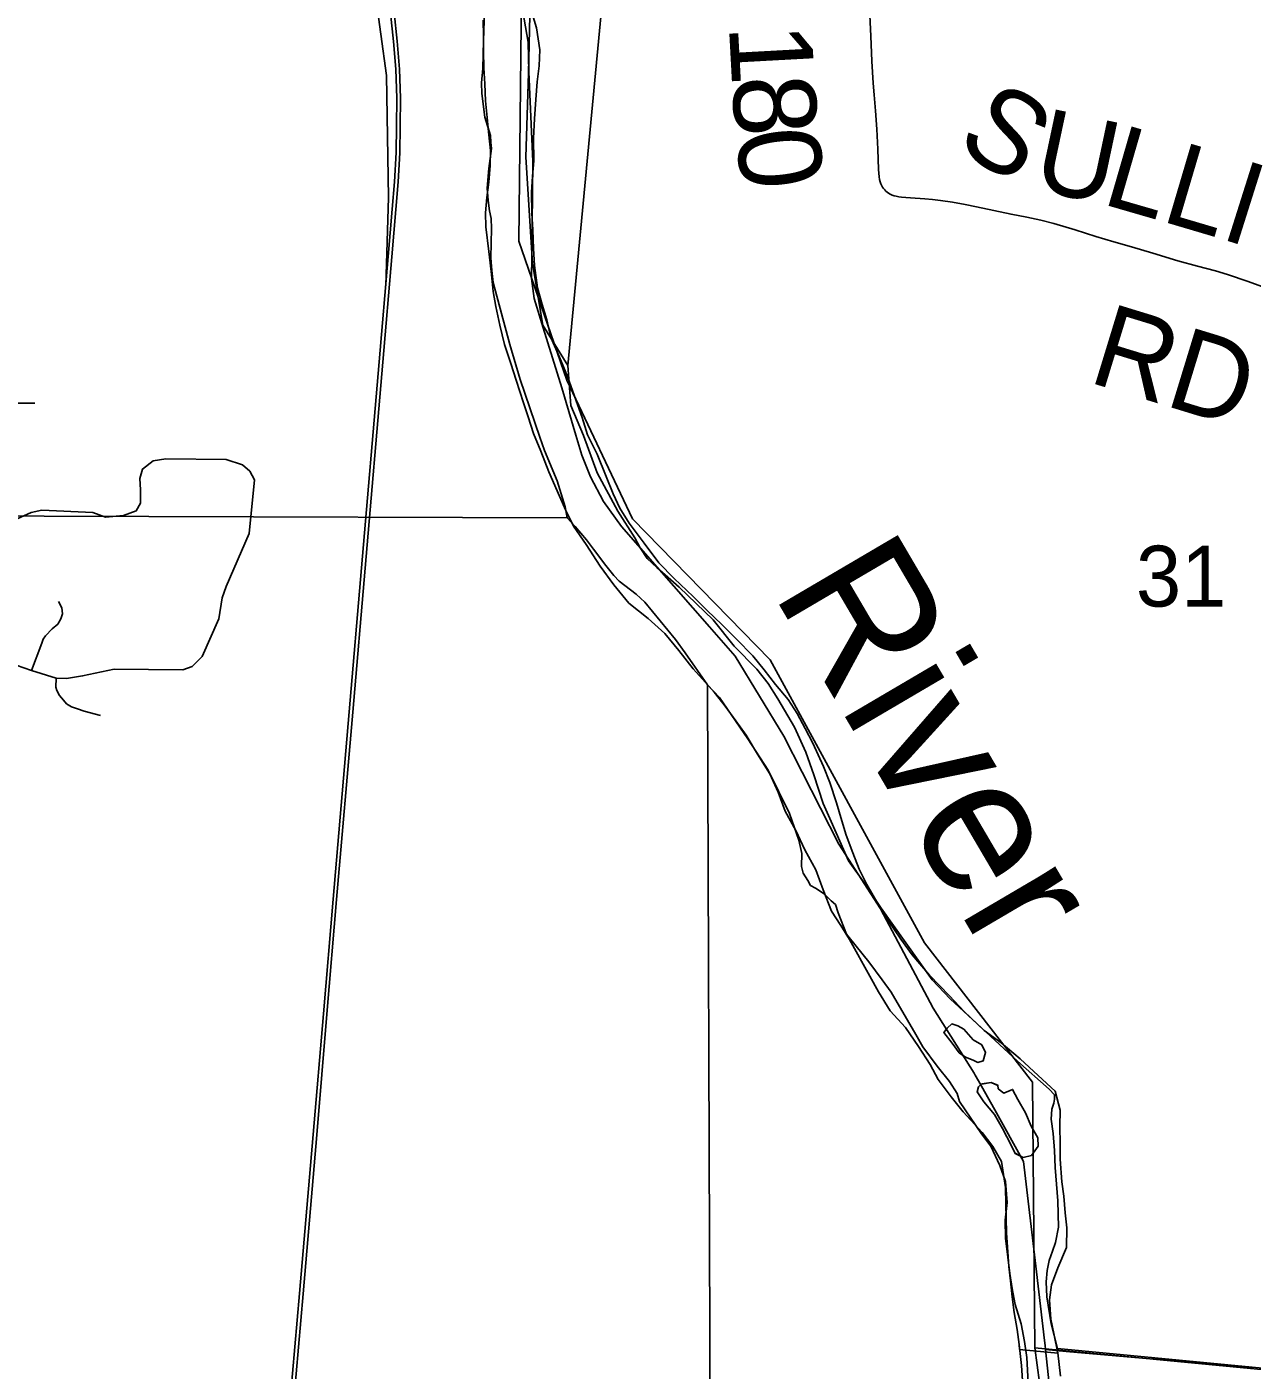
# Model space of a CAD drawing. Extents: x -38.1 to 35.9, y -2.7 to 28.5.
# Drawn here: x 9.678 to 10.521, y 15.282 to 16.206 of the extents above; entities that cross this region are included whole.
import ezdxf

# ---------------------------------------------------------------- set-up
doc = ezdxf.new("R2010")
doc.units = 0
for name, color, linetype in [('GM_X_City_Street', 7, 'Continuous'), ('GM_X_City_Street_Text', 7, 'Continuous'), ('GM_X_Corporation', 7, 'Continuous'), ('GM_X_Minor_River', 7, 'Continuous'), ('GM_X_Township', 7, 'Continuous'), ('GM_X_Township_Road', 7, 'Continuous'), ('GM_X_Township_Road_Text', 7, 'Continuous'), ('GM_X_US_Route', 7, 'Continuous')]:
    doc.layers.add(name, color=color, linetype=linetype)

msp = doc.modelspace()

# ---------------------------------------------------------------- linework, layer by layer
at = {"layer": 'GM_X_City_Street'}
msp.add_line((9.60584, 15.94704), (9.68311, 15.94727), dxfattribs=at)
for points in [[(9.73174, 15.86897), (9.7441, 15.87012), (9.75288, 15.87335), (9.75565, 15.87844), (9.75565, 15.88768), (9.75519, 15.89553), (9.75704, 15.902), (9.76443, 15.90754), (9.7732, 15.90893), (9.81479, 15.90847), (9.82587, 15.90477), (9.83095, 15.90061), (9.83419, 15.89461), (9.83049, 15.85765), (9.81479, 15.82115), (9.81201, 15.8133), (9.8097, 15.79898), (9.79815, 15.7731), (9.79122, 15.76617), (9.78476, 15.76386), (9.73763, 15.76432), (9.71592, 15.75971), (9.70483, 15.75785), (9.69768, 15.75819), (9.68081, 15.7634), (9.67018, 15.76709)], [(9.5552, 15.76108), (9.59724, 15.7849), (9.6291, 15.80091), (9.65875, 15.85372), (9.66845, 15.86666), (9.68046, 15.8722), (9.68785, 15.87359), (9.72297, 15.8722), (9.73174, 15.86897)], [(9.68081, 15.7634), (9.68796, 15.7823), (9.68877, 15.78505), (9.69036, 15.78733), (9.69505, 15.79213), (9.69882, 15.79522), (9.70088, 15.79888), (9.70202, 15.8023), (9.70157, 15.80664), (9.69939, 15.81099)], [(9.69768, 15.75819), (9.69756, 15.7519), (9.69814, 15.74961), (9.70008, 15.7463), (9.70271, 15.74299), (9.70488, 15.74059), (9.70819, 15.73853), (9.71231, 15.73704), (9.71699, 15.73556), (9.72819, 15.73248)]]:
    msp.add_lwpolyline(points, dxfattribs=at)
at = {"layer": 'GM_X_City_Street_Text'}
msp.add_lwpolyline([(10.53217, 16.02561), (10.51766, 16.03103), (10.50355, 16.03584), (10.49522, 16.03836), (10.48288, 16.04153), (10.46932, 16.04523), (10.45214, 16.05033), (10.4375, 16.05469), (10.42541, 16.05822), (10.41301, 16.06192), (10.39879, 16.06644), (10.38415, 16.0708), (10.37503, 16.07302), (10.36549, 16.07508), (10.35464, 16.07721), (10.33092, 16.08225), (10.32301, 16.08397), (10.31443, 16.08548), (10.30615, 16.08666), (10.30072, 16.08732), (10.2953, 16.0878), (10.28537, 16.08839), (10.28229, 16.0886), (10.27928, 16.08888), (10.27748, 16.08913), (10.27569, 16.08952), (10.27427, 16.08991), (10.27288, 16.09039), (10.27156, 16.09098), (10.27031, 16.09173), (10.26938, 16.09237), (10.26849, 16.09313), (10.2677, 16.09394), (10.26693, 16.09482), (10.26625, 16.09583), (10.26569, 16.09679), (10.26511, 16.09805), (10.26462, 16.09952), (10.2642, 16.10113), (10.26389, 16.10303), (10.26363, 16.10545), (10.26347, 16.10789), (10.26304, 16.12183), (10.26236, 16.13581), (10.2614, 16.14822), (10.26043, 16.15936), (10.25982, 16.1674), (10.25885, 16.18237), (10.25811, 16.19959), (10.25688, 16.22875)], dxfattribs=at)
at = {"layer": 'GM_X_Corporation'}
for points in [[(9.85708, 15.24325), (9.86514, 15.33495), (9.87448, 15.44434), (9.88156, 15.52741), (9.88821, 15.6061), (9.89925, 15.73502), (9.90774, 15.83395), (9.92005, 15.97561), (9.92614, 16.04821), (9.92897, 16.08076), (9.93052, 16.09954), (9.93165, 16.11955), (9.93193, 16.13775), (9.93207, 16.15707), (9.93137, 16.17692), (9.92982, 16.19608), (9.9277, 16.21552), (9.92461, 16.23622), (9.92094, 16.2551), (9.91544, 16.27995), (9.89514, 16.36362), (9.8727, 16.45304), (9.86749, 16.48978)], [(9.92443, 16.02788), (9.92629, 16.08872), (9.92498, 16.17257), (9.91709, 16.22978)], [(9.85955, 15.24303), (9.86762, 15.33473), (9.87696, 15.44413), (9.88403, 15.5272), (9.89069, 15.60589), (9.90172, 15.73481), (9.91022, 15.83373), (9.92253, 15.9754), (9.92861, 16.048), (9.93144, 16.08055), (9.933, 16.09937), (9.93413, 16.11946), (9.93442, 16.13772), (9.93456, 16.15711), (9.93385, 16.17706), (9.93229, 16.19631), (9.93017, 16.21584)]]:
    msp.add_lwpolyline(points, dxfattribs=at)
at = {"layer": 'GM_X_Township_Road'}
msp.add_line((10.36055, 15.29651), (10.38673, 15.29404), dxfattribs=at)
for points in [[(10.39098, 15.40191), (10.38961, 15.4118), (10.38834, 15.42738), (10.38851, 15.438), (10.38831, 15.44977), (10.38849, 15.46115), (10.3849, 15.47411), (10.3733, 15.48492), (10.36095, 15.4965), (10.34784, 15.50734), (10.3362, 15.51587), (10.32236, 15.529), (10.31228, 15.53978), (10.29846, 15.55404), (10.28653, 15.5679), (10.27873, 15.57865), (10.26908, 15.59284), (10.26316, 15.60281), (10.2554, 15.61621), (10.25026, 15.62692), (10.24587, 15.63799), (10.24113, 15.65021), (10.23825, 15.66013), (10.23464, 15.67233), (10.22993, 15.68645), (10.22555, 15.69752), (10.21821, 15.71358), (10.21305, 15.72353), (10.20752, 15.73386), (10.20121, 15.74345), (10.19265, 15.75383), (10.18483, 15.76382), (10.17701, 15.77344), (10.1658, 15.785), (10.15571, 15.79503), (10.14561, 15.80468), (10.13589, 15.81432), (10.1228, 15.82668), (10.11234, 15.83747), (10.1023, 15.85091), (10.09189, 15.86474), (10.0856, 15.87509), (10.08082, 15.88503), (10.07607, 15.89687), (10.06986, 15.91215), (10.06324, 15.92554), (10.05962, 15.93737), (10.05307, 15.95531), (10.04944, 15.96561), (10.04395, 15.97898), (10.03809, 15.99236), (10.03524, 16.00455), (10.03199, 16.01523), (10.02876, 16.02667), (10.02672, 16.04188), (10.02614, 16.05365), (10.02559, 16.06657), (10.02501, 16.07796), (10.02485, 16.09238), (10.0254, 16.10338), (10.02633, 16.11399), (10.02619, 16.12956), (10.02678, 16.14283), (10.02775, 16.1561), (10.0287, 16.16823), (10.03001, 16.17921), (10.03056, 16.19021), (10.02814, 16.20543), (10.02526, 16.21534)], [(10.39106, 15.40199), (10.38961, 15.4118), (10.38834, 15.42738), (10.38851, 15.438), (10.38831, 15.44977), (10.38849, 15.46115), (10.3849, 15.47411), (10.3733, 15.48492), (10.36095, 15.4965), (10.34784, 15.50734), (10.3362, 15.51587), (10.32236, 15.529), (10.31228, 15.53978), (10.29846, 15.55404), (10.28653, 15.5679), (10.27873, 15.57865), (10.26908, 15.59284), (10.26316, 15.60281), (10.2554, 15.61621), (10.25026, 15.62692), (10.24587, 15.63799), (10.24113, 15.65021), (10.23825, 15.66013), (10.23464, 15.67233), (10.22993, 15.68645), (10.22555, 15.69752), (10.21821, 15.71358), (10.21305, 15.72353), (10.20752, 15.73386), (10.20121, 15.74345), (10.19265, 15.75383), (10.18483, 15.76382), (10.17701, 15.77344), (10.1658, 15.785), (10.15571, 15.79503), (10.14561, 15.80468), (10.13589, 15.81432), (10.1228, 15.82668), (10.11234, 15.83747), (10.1023, 15.85091), (10.09189, 15.86474), (10.0856, 15.87509), (10.08082, 15.88503), (10.07607, 15.89687), (10.06986, 15.91215), (10.06324, 15.92554), (10.05962, 15.93737), (10.05307, 15.95531), (10.04944, 15.96561), (10.04395, 15.97898), (10.03809, 15.99236), (10.03524, 16.00455), (10.03199, 16.01523), (10.02876, 16.02667), (10.02672, 16.04188), (10.02614, 16.05365), (10.02559, 16.06657), (10.02501, 16.07796), (10.02485, 16.09238), (10.0254, 16.10338), (10.02633, 16.11399), (10.02619, 16.12956), (10.02678, 16.14283), (10.02775, 16.1561), (10.0287, 16.16823), (10.03001, 16.17921), (10.03056, 16.19021), (10.02814, 16.20543), (10.02526, 16.21534)], [(9.9914, 16.21057), (9.99161, 16.19956), (9.99183, 16.18931), (9.99203, 16.17792), (9.99261, 16.16691), (9.99319, 16.15513), (9.99415, 16.14373), (9.99513, 16.13385), (9.99645, 16.12093), (9.99629, 16.11068), (9.99535, 16.09931), (9.99405, 16.0887), (9.99312, 16.07809), (9.99335, 16.0686), (9.99536, 16.05149), (9.99704, 16.0378), (9.99835, 16.02412), (10.00009, 16.01384), (10.00292, 16.00089), (10.00613, 15.98756), (10.01048, 15.97459), (10.0141, 15.96314), (10.01917, 15.9475), (10.02243, 15.93796), (10.02605, 15.92652), (10.03117, 15.91429), (10.03665, 15.90016), (10.04397, 15.88334), (10.04837, 15.87341), (10.05352, 15.8627), (10.06243, 15.85003), (10.07207, 15.83508), (10.08136, 15.82241), (10.09179, 15.80971), (10.10491, 15.79926), (10.11651, 15.78883), (10.1262, 15.77729), (10.13587, 15.76461), (10.15043, 15.74844), (10.15787, 15.73883), (10.1653, 15.72884), (10.17236, 15.71886), (10.18013, 15.70584), (10.18865, 15.69242), (10.19452, 15.6798), (10.19925, 15.66682), (10.20664, 15.65342), (10.21288, 15.64004), (10.22026, 15.62626), (10.22536, 15.61252), (10.2312, 15.598), (10.2375, 15.58803), (10.24342, 15.57845), (10.25745, 15.55318), (10.26336, 15.54246), (10.2715, 15.52943), (10.28195, 15.51788), (10.29086, 15.50483), (10.29902, 15.49256), (10.30455, 15.48222), (10.31347, 15.47032), (10.32166, 15.45994), (10.33472, 15.44569), (10.34217, 15.43608), (10.34808, 15.42574), (10.35083, 15.40786), (10.35104, 15.39647)], [(10.32217, 15.51685), (10.31803, 15.5192), (10.31388, 15.5204), (10.31079, 15.51741), (10.30847, 15.51442), (10.31405, 15.50712), (10.31888, 15.50059), (10.32339, 15.49748), (10.32867, 15.4955), (10.33168, 15.49393), (10.3355, 15.49501), (10.3371, 15.50068), (10.33453, 15.50603)], [(10.33453, 15.50603), (10.32851, 15.50954), (10.32217, 15.51685)], [(10.33443, 15.47911), (10.33218, 15.47723), (10.33137, 15.47382), (10.33582, 15.46692), (10.34327, 15.45807), (10.34881, 15.4485), (10.35471, 15.43702), (10.35751, 15.43144)], [(10.33432, 15.47902), (10.33218, 15.47723), (10.33137, 15.47382), (10.33582, 15.46692), (10.34327, 15.45807), (10.34881, 15.4485), (10.35471, 15.43702), (10.35759, 15.43128)], [(10.34548, 15.47816), (10.34096, 15.48012), (10.33432, 15.47902)], [(10.34556, 15.47824), (10.34096, 15.48012), (10.33443, 15.47911)], [(10.37301, 15.44204), (10.36858, 15.45008), (10.36455, 15.45926), (10.35937, 15.46844), (10.35569, 15.47534), (10.34957, 15.47278), (10.34582, 15.47587), (10.34548, 15.47816)], [(10.37309, 15.44212), (10.36858, 15.45008), (10.36455, 15.45926), (10.35937, 15.46844), (10.35569, 15.47534), (10.34957, 15.47278), (10.34582, 15.47587), (10.34556, 15.47824)], [(10.35751, 15.43144), (10.36293, 15.42854), (10.36864, 15.42997), (10.3733, 15.43634), (10.37309, 15.44212)], [(10.35759, 15.43128), (10.36293, 15.42854), (10.36864, 15.42997), (10.3733, 15.43634), (10.37301, 15.44204)], [(10.38681, 15.29414), (10.38419, 15.30752), (10.38206, 15.31742), (10.38113, 15.33072), (10.38243, 15.34095), (10.38679, 15.35264), (10.3927, 15.36659), (10.39292, 15.38025), (10.39194, 15.39051), (10.39106, 15.40199)], [(10.38673, 15.29404), (10.38419, 15.30752), (10.38206, 15.31742), (10.38113, 15.33072), (10.38243, 15.34095), (10.38679, 15.35264), (10.3927, 15.36659), (10.39292, 15.38025), (10.39194, 15.39051), (10.39098, 15.40191)], [(10.35104, 15.39647), (10.35149, 15.37673), (10.35209, 15.36686), (10.35302, 15.35356), (10.35438, 15.34367), (10.35535, 15.33265), (10.3567, 15.322), (10.3588, 15.3102), (10.36015, 15.29994), (10.36055, 15.29651)], [(10.35104, 15.39647), (10.35149, 15.37673), (10.35209, 15.36686), (10.35302, 15.35356), (10.35438, 15.34367), (10.35535, 15.33265), (10.3567, 15.322), (10.3588, 15.3102), (10.36015, 15.29994), (10.36183, 15.28549), (10.36242, 15.27523)], [(10.38866, 15.27823), (10.38681, 15.29414)]]:
    msp.add_lwpolyline(points, dxfattribs=at)
at = {"layer": 'GM_X_US_Route'}
for points in [[(10.52889, 15.2826), (10.37102, 15.29767), (10.36932, 15.48046), (10.29514, 15.57613), (10.189, 15.77088), (10.09428, 15.86768), (10.04901, 15.96298), (10.01591, 16.05865), (10.01817, 16.25038), (9.98164, 16.44212), (9.94205, 16.82904), (9.92, 16.92473), (9.90592, 17.11651), (10.03218, 17.30791), (10.04811, 17.35207), (10.11434, 17.49894), (10.24367, 17.69038), (10.3361, 17.78534)], [(10.3361, 17.78534), (10.24367, 17.69038), (10.11434, 17.49894), (10.04811, 17.35207), (10.03218, 17.30791), (9.90592, 17.11651), (9.92, 16.92473), (9.94205, 16.82904), (9.98164, 16.44212), (10.01817, 16.25038), (10.01591, 16.05865), (10.04901, 15.96298), (10.09428, 15.86768), (10.189, 15.77088), (10.29514, 15.57613), (10.36932, 15.48046), (10.37102, 15.29767), (10.52889, 15.2826)], [(10.37741, 15.25), (10.37102, 15.29767), (10.36932, 15.48046), (10.29514, 15.57613), (10.189, 15.77088), (10.09428, 15.86768), (10.04901, 15.96298), (10.01591, 16.05865), (10.01817, 16.25038), (9.98164, 16.44212), (9.94205, 16.82904), (9.92, 16.92473), (9.90592, 17.11651), (10.03218, 17.30791), (10.04811, 17.35207), (10.11434, 17.49894), (10.24367, 17.69038), (10.3361, 17.78534)], [(10.3361, 17.78534), (10.24367, 17.69038), (10.11434, 17.49894), (10.04811, 17.35207), (10.03218, 17.30791), (9.90592, 17.11651), (9.92, 16.92473), (9.94205, 16.82904), (9.98164, 16.44212), (10.01817, 16.25038), (10.01591, 16.05865), (10.04901, 15.96298), (10.09428, 15.86768), (10.189, 15.77088), (10.29514, 15.57613), (10.36932, 15.48046), (10.37102, 15.29767), (10.52889, 15.2826)], [(10.38391, 15.24505), (10.37837, 15.29645), (10.37807, 15.29923), (10.3777, 15.30262), (10.37214, 15.34997), (10.36323, 15.4258), (10.3434, 15.46127), (10.33226, 15.48119), (10.32999, 15.48527), (10.32932, 15.48647), (10.30107, 15.53131), (10.26492, 15.59944), (10.26491, 15.59945), (10.23609, 15.64391), (10.19824, 15.71821), (10.16486, 15.77326), (10.14716, 15.79344), (10.08666, 15.86246), (10.07438, 15.87957), (10.06535, 15.89655), (10.0594, 15.91155), (10.05521, 15.92522), (10.04568, 15.9578), (10.03266, 15.99897), (10.02667, 16.01934), (10.02476, 16.033), (10.025, 16.04834), (10.02572, 16.11352), (10.02284, 16.17511), (10.02236, 16.19548), (9.99673, 16.3431)], [(10.98915, 15.23941), (10.38665, 15.29731), (10.38233, 15.31411), (10.37927, 15.33273), (10.3787, 15.34296), (10.3796, 15.3509), (10.38087, 15.35769), (10.38326, 15.36408), (10.38527, 15.37011), (10.38735, 15.38067), (10.38694, 15.39886), (10.38509, 15.42162), (10.38455, 15.43337), (10.38364, 15.44513), (10.38231, 15.455), (10.38281, 15.46181), (10.38403, 15.46595), (10.38446, 15.46859), (10.38451, 15.47162), (10.3808, 15.47548), (10.35919, 15.49482), (10.31265, 15.53772), (10.3004, 15.55083), (10.28232, 15.57616), (10.26534, 15.59996), (10.25503, 15.61568), (10.24285, 15.63257), (10.23086, 15.65969), (10.22541, 15.67191), (10.21896, 15.69172), (10.21357, 15.70735), (10.20556, 15.72454), (10.19418, 15.74407), (10.18756, 15.75442), (10.17979, 15.76441), (10.16419, 15.78023), (10.14975, 15.7983), (10.12631, 15.8207), (10.11104, 15.83424), (10.10434, 15.84043), (10.09955, 15.84771), (10.09589, 15.8546), (10.08411, 15.873), (10.06984, 15.89939), (10.06047, 15.92495), (10.05176, 15.94556), (10.04963, 15.97325), (10.08361, 16.33202)], [(9.99246, 16.21708), (9.99169, 16.19664), (9.99133, 16.17733), (9.99039, 16.1675), (9.99064, 16.1603), (9.99261, 16.14398), (9.99653, 16.1314), (9.99682, 16.12648), (9.99712, 16.12231), (9.99536, 16.10871), (9.99434, 16.09509), (9.99494, 16.08675), (9.99594, 16.07953), (9.99698, 16.07421), (9.99723, 16.06739), (9.99686, 16.04733), (9.99745, 16.0386), (9.99843, 16.03025), (10.00976, 15.98763), (10.01688, 15.96363), (10.03053, 15.92399), (10.03377, 15.91484), (10.04246, 15.89384), (10.04781, 15.87595), (10.04919, 15.86835), (9.18574, 15.87123)], [(10.14892, 14.86249), (10.14589, 15.75368), (10.15405, 15.74482), (10.17359, 15.71643), (10.18759, 15.69496), (10.20218, 15.66514), (10.20865, 15.64684), (10.21075, 15.63771), (10.21058, 15.62863), (10.21163, 15.62407), (10.21495, 15.61908), (10.21678, 15.61564), (10.22015, 15.61368), (10.22614, 15.60978), (10.23098, 15.60515), (10.23395, 15.60244), (10.23574, 15.59672), (10.24153, 15.58223), (10.24819, 15.57377), (10.2567, 15.56301), (10.26593, 15.55071), (10.27221, 15.54226), (10.28909, 15.51317), (10.29386, 15.50474), (10.30384, 15.49131), (10.31235, 15.48092), (10.31749, 15.47249), (10.31929, 15.46716), (10.3344, 15.44491), (10.34068, 15.43646), (10.34687, 15.42309), (10.35083, 15.41203), (10.35208, 15.39762), (10.35071, 15.38553), (10.35085, 15.37302), (10.35381, 15.34873), (10.35551, 15.33847), (10.35758, 15.32745), (10.3615, 15.31412), (10.36392, 15.30196), (10.36561, 15.29094), (10.36642, 15.2735)], [(10.52889, 15.2826), (10.37102, 15.29767), (10.37741, 15.25)], [(10.5212, 15.28385), (10.48703, 15.28687), (10.4557, 15.28963), (10.39263, 15.2952), (10.38537, 15.29584), (10.37837, 15.29645), (10.38391, 15.24505)]]:
    msp.add_lwpolyline(points, dxfattribs=at)
for points in [[(10.08361, 16.33202), (10.04963, 15.97325), (10.03261, 16.00083), (10.02539, 16.04325), (10.02088, 16.11636), (10.02268, 16.17412), (10.02359, 16.21384), (10.01637, 16.24452), (10.01276, 16.29326), (10.00607, 16.33763)], [(9.15053, 15.87188), (9.18574, 15.87123), (10.04919, 15.86835), (10.05475, 15.86256), (10.06254, 15.85332), (10.06734, 15.8468), (10.07584, 15.83566), (10.08139, 15.82874), (10.08511, 15.82488), (10.09668, 15.81595), (10.10264, 15.81054), (10.12375, 15.78477), (10.13039, 15.77556), (10.14589, 15.75368), (10.14892, 14.86249), (9.14546, 14.87101)]]:
    msp.add_lwpolyline(points, close=True, dxfattribs=at)

# ---------------------------------------------------------------- texts
at = {"layer": 'GM_X_Minor_River'}
msp.add_text('31', height=0.041856, rotation=0.00001, dxfattribs=at).set_placement((10.44054, 15.80741))
at = {"layer": 'GM_X_Township'}
for s, height, rotation, p in [('1', 0.05682, 273.11101, (10.16051, 16.20714)), ('8', 0.05682, 273.88275, (10.16246, 16.17136)), ('S', 0.05682, 327.5791, (10.3152, 16.12372)), ('U', 0.05682, 347.99712, (10.36792, 16.09485)), ('L', 0.05682, 343.83356, (10.41577, 16.08472)), ('0', 0.05682, 276.6452, (10.16511, 16.13346)), ('L', 0.05682, 343.52243, (10.45651, 16.07291)), ('I', 0.05682, 342.45739, (10.497, 16.06094)), ('RD', 0.056818, 342.97572, (10.40656, 15.96216))]:
    msp.add_text(s, height=height, rotation=rotation, dxfattribs=at).set_placement(p)
at = {"layer": 'GM_X_Township_Road_Text'}
msp.add_text('River', height=0.094669, rotation=300.43133, dxfattribs=at).set_placement((10.18983, 15.81755))

doc.saveas('drawing.dxf')
